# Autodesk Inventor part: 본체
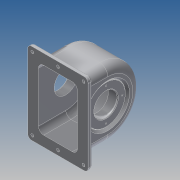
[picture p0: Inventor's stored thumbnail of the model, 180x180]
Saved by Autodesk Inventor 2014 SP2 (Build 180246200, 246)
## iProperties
Created: 2015-09
Part Number: 본체
Material: 알루미늄 6061
Document SubType Name: Modeling
Designer: 201-17
Density: 2.71 g/cm^3
Appearance: 알루미늄 - 평지
Mass: 676.408 g
Surface Area: 897.073 cm^2
Volume: 249.597 cm^3
Author: 201-17
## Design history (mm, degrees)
sketch "스케치1"
  geometry: L1 (-38.5, 0)-(38.5, 0); L2 (38.5, 0)-(38.5, 43); L3 (24.5, 57)-(-24.5, 57); L4 (-38.5, 43)-(-38.5, 0); L5 (-24.5, 52)-(24.5, 52); L6 (33.5, 43)-(33.5, 0); L7 (-33.5, 0)-(-33.5, 43); A1 r 14 centre (-24.5, 43) between (-24.5, 57) and (-38.5, 43); A2 r 14 centre (24.5, 43) between (38.5, 43) and (24.5, 57); A3 r 9 centre (24.5, 43) between (33.5, 43) and (24.5, 52); A4 r 9 centre (-24.5, 43) between (-24.5, 52) and (-33.5, 43); 3 further points
  constraints: 14 end point, 8 point on circle, 6 point on line, 4 centre point, 4 tangent, 3 parallel, 1 equal radius, 1 horizontal, 1 perpendicular, 1 other
  dimensions: "d0" = 77 distance of point (38.5, 57) point (-38.5, 57); "d1" = 57 distance of point (-38.5, 57) L1.start; "d2" = 0 vertical distance of L1.start point (0, 0); "d3" = 38.5 distance of L1.start point (0, 0) (= 0.5 x d0); "d4" = 14 radius of A1; "d5" = 5 distance between parallel lines of L5 L3; "d6" = 9 radius of A4; "d7" = 43 distance of L7.start L7.end; "d8" = 43 distance of L6.start L6.end; "d9" = 33.5 distance of point (0, 0) L6.end
revolve "회전1" sketch "스케치1" stored, may be unused: angle "d10" = 180 deg
sketch "스케치2"
  geometry: L1 (58, 14)-(58, 100) reference; L2 (0, 5)-(49, 5) reference; L3 (-9, 14)-(-9, 100) reference; L4 (0, 109)-(49, 109) reference; L5 (63, 14)-(63, 100) reference; L6 (49, 114)-(0, 114) reference; L7 (-14, 14)-(-14, 100) reference; L8 (49, 0)-(0, 0) reference; A1 r 9 centre (49, 14) between (49, 5) and (58, 14) reference; A2 r 9 centre (0, 14) between (-9, 14) and (0, 5) reference; A3 r 9 centre (0, 100) between (0, 109) and (-9, 100) reference; A4 r 9 centre (49, 100) between (58, 100) and (49, 109) reference; A5 r 14 centre (49, 100) between (63, 100) and (49, 114) reference; A6 r 14 centre (0, 100) between (0, 114) and (-14, 100) reference; A7 r 14 centre (0, 14) between (-14, 14) and (0, 0) reference; A8 r 14 centre (49, 14) between (49, 0) and (63, 14) reference; 1 further point
extrude "돌출1" join sketch "스케치2" distance "d11" = 47; taper "d12" = 0 deg
sketch "스케치3"
  geometry: L1 (-27.5, 127)-(76.5, 127); L2 (76.5, 127)-(76.5, -13); L3 (76.5, -13)-(-27.5, -13); L4 (-27.5, -13)-(-27.5, 127); L5 (-27.5, 127)-(76.5, -13); L6 (76.5, 127)-(-27.5, -13); L7 (0, 0)-(49, 0) reference; L8 (63, 14)-(63, 100) reference; L9 (49, 114)-(0, 114) reference; L10 (-14, 100)-(-14, 14) reference; A1 r 14 centre (49, 14) between (49, 0) and (63, 14) reference; A2 r 14 centre (49, 100) between (63, 100) and (49, 114) reference; A3 r 14 centre (0, 100) between (0, 114) and (-14, 100) reference; A4 r 14 centre (0, 14) between (-14, 14) and (0, 0) reference; 1 further point
  constraints: 12 end point, 2 midpoint, 2 parallel, 1 horizontal, 1 perpendicular
  dimensions: "d13" = 104 distance of L2.end L3.end; "d14" = 140 distance of L1.end L2.end
extrude "돌출2" join sketch "스케치3" distance "d15" = 7; taper "d16" = 0 deg
fillet "모깎기1" dims "d17" = 7
sketch "스케치4"
  geometry: C1 r 31 at (0, 0); 1 further point
  constraints: 1 centre point, 1 coincident
  dimensions: "d18" = 62 diameter of C1
extrude "돌출3" join sketch "스케치4" distance "d19" = 10; taper "d20" = 0 deg
hole "구멍1" diameter "d23" = 40; stored, may be unused: countersink angle "d27" = 90 deg, drill point angle "d29" = 0 deg; dims "d21" = 10, "d22" = 10, "d24" = 6, "d25" = 4, "d26" = 2, "d28" = 8
node "작업 평면1"
sketch "스케치5"
  geometry: C1 r 28 at (0, 0); 1 further point
  constraints: 1 centre point, 1 coincident
  dimensions: "d31" = 56 diameter of C1
extrude "돌출4" join sketch "스케치5" stored distance "d32" = 10; taper "d33" = 40 deg
hole "구멍2" diameter "d36" = 40; stored, may be unused: countersink angle "d40" = 90 deg, drill point angle "d42" = 0 deg; dims "d37" = 6, "d38" = 4, "d39" = 2, "d41" = 16, "d54" = 10, "d55" = 10
sketch "스케치6"
  geometry: L1 (-24.5, 0)-(24.5, 0) reference; L2 (38.5, 0)-(-47.831, 0); L3 (38.5, 0)-(38.5, 43) reference; L4 (35.5, 20)-(35.5, -20) reference; L5 (35.5, 20)-(19.5, 20) reference; L6 (24.5, 0)-(33.5, 0) reference; L7 (24.5, 0)-(24.5, 0) reference; L8 (24.5, 0)-(33.5, 0) reference; L9 (33.5, 0)-(33.5, 0) reference; L10 (19.5, 28)-(33.5, 39.747) reference; L11 (34.5, 34.059)-(38.5, 37.416); L12 (35.5, 0)-(35.5, 33); L13 (35.5, 33)-(34.5, 33); L14 (38.5, 37.416)-(38.5, 0); L15 (34.5, 34.059)-(34.5, 33); L16 (35.5, 0)-(38.5, 0); 1 further point
  constraints: 14 end point, 4 parallel, 2 collinear, 2 point on line
  dimensions: "d45" = 5 distance between parallel lines of L11 L10; "d47" = 3 distance from line of L12 L3.start; "d48" = 86.33059 distance of L2.start L2.end; "d49" = 1 distance of L12.end L13.end; "d50" = 33 distance between parallel lines of L1 L13; "d51" = 0 distance from line of point (0, 0) L2; "d52" = 0 distance from line of L1 L12.start
revolve "회전2" sketch "스케치6" stored, may be unused: angle "d53" = 180 deg
sketch "스케치7"
  geometry: 2 further points
  dimensions: "d56" = 24 distance of point (0, 24) point (0, 0); "d57" = 0 horizontal distance of point (0, 0) point (0, 24)
hole "구멍3" sketch "스케치7" at (0, 24) diameter "d58" = 2.459; stored, may be unused: countersink angle "d62" = 90 deg, drill point angle "d64" = 118 deg; dims "d59" = 6, "d60" = 4, "d61" = 2, "d63" = 8
node "작업축1"
sketch "스케치8"
  geometry: 2 further points
  dimensions: "d68" = 28 distance of point (0, 0) point (0, 28); "d69" = 0 horizontal distance of point (0, 0) point (0, 28)
hole "구멍4" sketch "스케치8" at (0, 28) diameter "d70" = 2.459; stored, may be unused: countersink angle "d74" = 90 deg, drill point angle "d76" = 118 deg; dims "d71" = 7, "d72" = 4, "d73" = 2, "d75" = 9
node "작업 평면3"
  node "작업 평면2"
sketch "스케치9"
  geometry: C1 r 6 at (0, 0); 1 further point
  constraints: 1 centre point, 1 coincident
  dimensions: "d81" = 12 diameter of C1
extrude "돌출5" join sketch "스케치9" stored distance "d82" = 12; taper "d83" = 10 deg
hole "구멍5" diameter "d86" = 4.459; stored, may be unused: countersink angle "d90" = 90 deg, drill point angle "d92" = 118 deg; dims "d87" = 7, "d88" = 4, "d89" = 2, "d91" = 9, "d115" = 10, "d116" = 10
sketch "스케치10"
  geometry: L1 (76.5, -120)-(76.5, 6) reference; 4 further points
  dimensions: "d93" = 62 vertical distance of point (24.5, -57) point (-19.5, -119); "d94" = 44 distance of point (24.5, -119) point (-19.5, -119); "d95" = 44 distance of point (68.5, -119) point (24.5, -119) (= d94); "d96" = 62 vertical distance of point (24.5, -57) point (68.5, -119) (= d93); "d97" = 62 distance of point (24.5, -57) point (24.5, -119) (= d93); "d105" = 8 distance from line of point (68.5, -119) L1
hole "구멍6" sketch "스케치10" at (-19.5, -119), (24.5, -119), (68.5, -119) diameter "d98" = 5; stored, may be unused: countersink angle "d102" = 90 deg, drill point angle "d104" = 0 deg; dims "d99" = 5, "d100" = 4, "d101" = 2, "d103" = 9
sketch "스케치11"
  geometry: L1 (-20.5, -47)-(69.5, -47) reference; L2 (-14, 0)-(-14, -40) reference; 2 further points
  constraints: 1 other
  dimensions: "d106" = 30 distance from line of L1 point (24.5, -17); "d107" = 38.5 distance from line of L2 point (24.5, -17)
feature "엠보싱1" sketch "스케치11" dims "d0" = 77, "d1" = 57, "d2" = 0, "d3" = 38.5 (= 0.5 x d0), "d4" = 14, "d5" = 5, "d6" = 9, "d7" = 43, "d8" = 43, "d9" = 33.5, "d108" = 0.5, "d109" = 0
fillet "모깎기2" dims "d110" = 0.5
fillet "모깎기3" dims "d111" = 3, "d117" = 1
chamfer "모따기1" distance "d112" = 1; stored, may be unused: second distance "d113" = 2, angle "d114" = 45 deg
node "솔리드1"
pattern_circular "원형 패턴1" dims angle "d66" = 360 deg
pattern_circular "원형 패턴2" dims angle "d78" = 360 deg
mirror "대칭1"
node "투영된 루프1"
node "투영된 루프2"
other parameters: "d30" = -19, "d46" = 33, "d80" = -6
